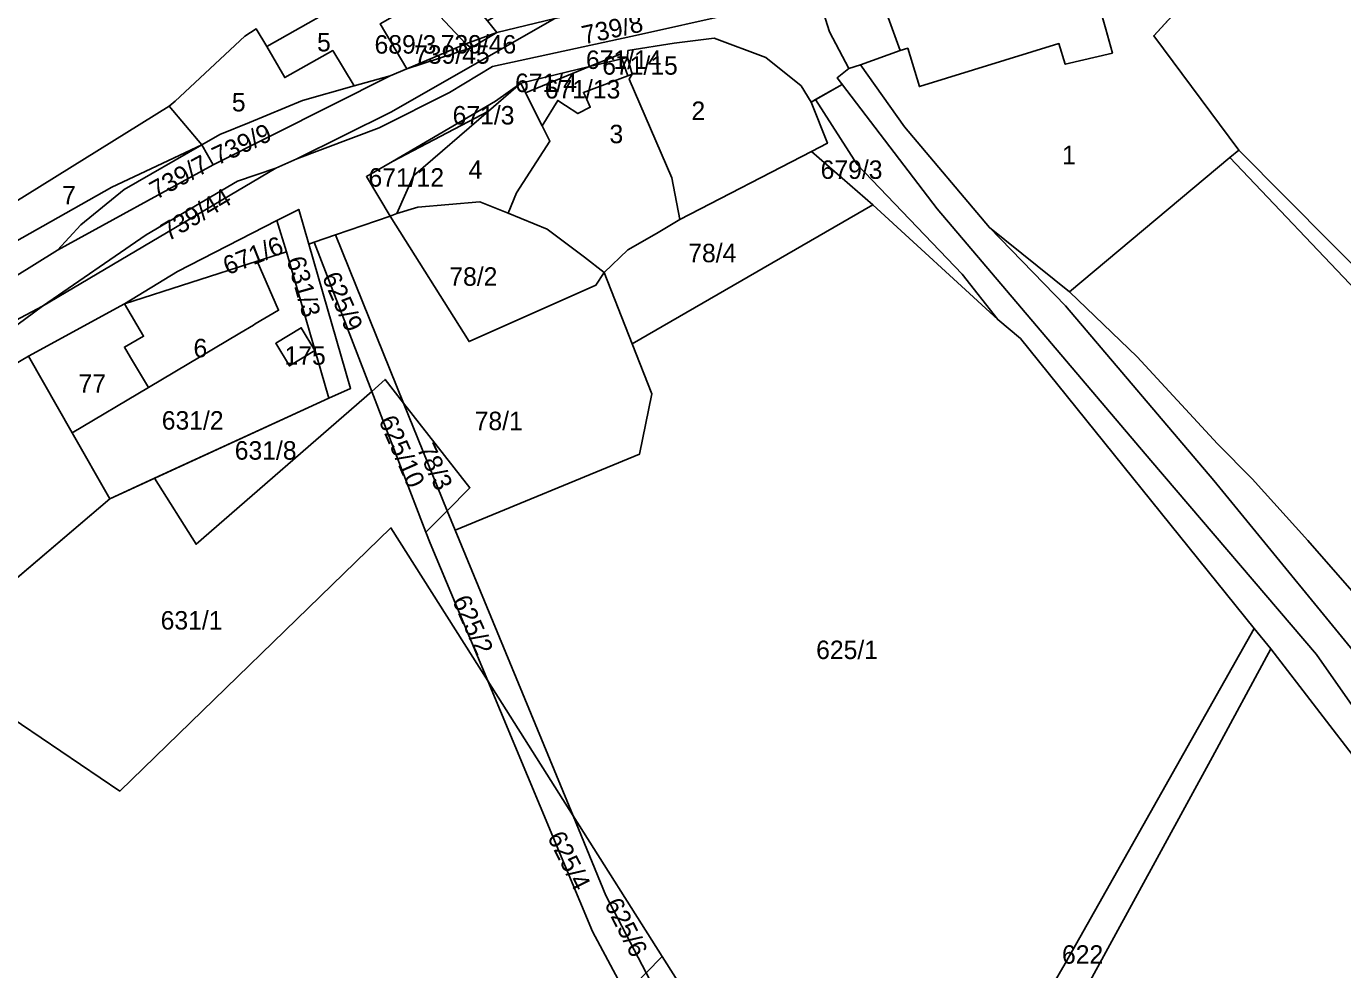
# Model space of a CAD drawing. Extents: x -629983 to -626385, y -1072828 to -1067897.
# Drawn here: x -627150.4 to -626936.7, y -1070299.1 to -1070145.8 of the extents above; entities that cross this region are included whole.
import ezdxf

# ---------------------------------------------------------------- set-up
doc = ezdxf.new("R2010")
doc.units = 0
for name, color, linetype in [('Cesty', 7, 'Continuous'), ('Parcela nároku', 7, 'Continuous'), ('Parcelní číslo', 7, 'Continuous'), ('Plocha PÚ', 7, 'Continuous'), ('Vnitřní obvod_šetřený', 7, 'Continuous')]:
    doc.layers.add(name, color=color, linetype=linetype)

msp = doc.modelspace()

# ---------------------------------------------------------------- linework, layer by layer
at = {"layer": 'Cesty'}
msp.add_lwpolyline([(-626828.5, -1070436.77), (-626845.9, -1070410.76), (-626860.5, -1070382.13), (-626889.8, -1070326.73), (-626898.73, -1070308.1), (-626940.88, -1070247.87), (-626967.82, -1070216.35), (-627002.5, -1070175.45), (-627018.74, -1070154.18)], dxfattribs=at)
at = {"layer": 'Parcela nároku'}
for points in [[(-626967.32, -1070147.34), (-626952.24, -1070130.82), (-626954.18, -1070128.3), (-626936.23, -1070115.91), (-626914.61, -1070101.46), (-626893.72, -1070087.44), (-626878.42, -1070105.68), (-626838.37, -1070153.8), (-626843.54, -1070157.06), (-626848.75, -1070159.57), (-626863.88, -1070171.76), (-626872.99, -1070179.12), (-626887.59, -1070189.96), (-626911.42, -1070210.64), (-626920.06, -1070200.25), (-626930.91, -1070188.7), (-626953.54, -1070165.93)], [(-627179.11, -1070102.43), (-627182.79, -1070129.31), (-627188.17, -1070161.97), (-627164.05, -1070181.7), (-627127.23, -1070158.76), (-627126.21, -1070157.99), (-627114.91, -1070147.41), (-627113.07, -1070146.24), (-627111.33, -1070149.11), (-627095.84, -1070140.28), (-627093.44, -1070138.91), (-627090.01, -1070136.88), (-627090.88, -1070135.94), (-627100.27, -1070127.84), (-627102.93, -1070125.54), (-627123.58, -1070112.62), (-627149.23, -1070101.19), (-627173.72, -1070092.7), (-627175.67, -1070092.02), (-627177.28, -1070091.46)], [(-626969.82, -1070116.29), (-626968.13, -1070119.78), (-626980.11, -1070128.81), (-626979.18, -1070131.84), (-626987.84, -1070134.27), (-626996.76, -1070136.77), (-627011.69, -1070140.96), (-627010.48, -1070144.38), (-627008.5, -1070149.71), (-627014.94, -1070152.06), (-627016.87, -1070152.66), (-627019.96, -1070146.7), (-627021.89, -1070140.64), (-627023.3, -1070136.2), (-627015.8, -1070134.43), (-626983.76, -1070126.87), (-626977.72, -1070122.1)], [(-627100.27, -1070127.84), (-627096.2, -1070123.68), (-627088.83, -1070130.5), (-627081.08, -1070138.25), (-627075.54, -1070144.91), (-627074.02, -1070146.81), (-627079.02, -1070148.65), (-627090.01, -1070136.88), (-627090.88, -1070135.94)], [(-627037.79, -1070128.95), (-627023.44, -1070126.11), (-627017.39, -1070132.64), (-627023.83, -1070134.57), (-627052.84, -1070139.54), (-627057.35, -1070140.58), (-627064.59, -1070144.52), (-627074.02, -1070146.81), (-627075.54, -1070144.91), (-627058.79, -1070134.99)], [(-626982.72, -1070148.62), (-626981.69, -1070151.96), (-626974.05, -1070150.14), (-626975.13, -1070146.29), (-626978.67, -1070133.67), (-626954.18, -1070128.3), (-626952.24, -1070130.82), (-626967.32, -1070147.34), (-626953.54, -1070165.93), (-626954.95, -1070167.11), (-626980.99, -1070188.96), (-626994.01, -1070178.49), (-627007.83, -1070162.13), (-627014.94, -1070152.06), (-627008.5, -1070149.71), (-627007.27, -1070149.36), (-627005.37, -1070155.59)], [(-626979.18, -1070131.84), (-626987.84, -1070134.27), (-626996.76, -1070136.77), (-627011.69, -1070140.96), (-627010.48, -1070144.38), (-627008.5, -1070149.71), (-627007.27, -1070149.36), (-627005.37, -1070155.59), (-626982.72, -1070148.62), (-626981.69, -1070151.96), (-626974.05, -1070150.14), (-626975.13, -1070146.29), (-626978.67, -1070133.67)], [(-627064.59, -1070144.52), (-627091.23, -1070159.74), (-627106.48, -1070167.33), (-627093.12, -1070162.31), (-627081.7, -1070156.55), (-627074.7, -1070152.35), (-627051, -1070147.18), (-627021.89, -1070140.64), (-627023.3, -1070136.2), (-627039.61, -1070139.4)], [(-627093.44, -1070138.91), (-627090.01, -1070136.88), (-627079.02, -1070148.65), (-627088.6, -1070152.71), (-627092.94, -1070145.4), (-627090.54, -1070144.04)], [(-627090.54, -1070144.04), (-627093.44, -1070138.91), (-627095.84, -1070140.28), (-627111.33, -1070149.11), (-627108.45, -1070154.14), (-627100.65, -1070149.75), (-627097.19, -1070155.5), (-627091.34, -1070153.87), (-627088.6, -1070152.71), (-627092.94, -1070145.4)], [(-627114.91, -1070147.41), (-627113.07, -1070146.24), (-627111.33, -1070149.11), (-627108.45, -1070154.14), (-627100.65, -1070149.75), (-627097.19, -1070155.5), (-627105.58, -1070157.84), (-627114.15, -1070161.41), (-627118.97, -1070163.38), (-627121.91, -1070165.06), (-627127.23, -1070158.76), (-627126.21, -1070157.99)], [(-627079.02, -1070148.65), (-627074.02, -1070146.81), (-627078.16, -1070149.32)], [(-627052.52, -1070154.39), (-627052.03, -1070153.59), (-627052.78, -1070150.86), (-627052.71, -1070149.76), (-627045.21, -1070148.52), (-627038.73, -1070147.72), (-627030.34, -1070150.88), (-627024.59, -1070155.47), (-627022.98, -1070158.1), (-627020.32, -1070164.81), (-627022.93, -1070166.16), (-627044.26, -1070177.17), (-627045.61, -1070170.42)], [(-627079.02, -1070148.65), (-627088.6, -1070152.71), (-627078.16, -1070149.32)], [(-627058.98, -1070152.35), (-627053.98, -1070150.32), (-627053.72, -1070151.09)], [(-627070.13, -1070155.02), (-627058.98, -1070152.35), (-627069.34, -1070156.6)], [(-627058.98, -1070152.35), (-627053.72, -1070151.09), (-627052.73, -1070153.85), (-627059.94, -1070156.55), (-627059.55, -1070157.3), (-627058.84, -1070158.94), (-627060.83, -1070159.99), (-627062.86, -1070158.66), (-627064.1, -1070157.85), (-627066.63, -1070161.99), (-627069.34, -1070156.6)], [(-627053.72, -1070151.09), (-627052.78, -1070150.86), (-627052.03, -1070153.59), (-627052.73, -1070153.85)], [(-627118.97, -1070163.38), (-627114.15, -1070161.41), (-627105.58, -1070157.84), (-627097.19, -1070155.5), (-627091.34, -1070153.87), (-627120.06, -1070168.31), (-627121.91, -1070165.06)], [(-627066.63, -1070161.99), (-627064.1, -1070157.85), (-627062.86, -1070158.66), (-627060.83, -1070159.99), (-627058.84, -1070158.94), (-627059.55, -1070157.3), (-627059.94, -1070156.55), (-627052.73, -1070153.85), (-627052.03, -1070153.59), (-627052.52, -1070154.39), (-627045.61, -1070170.42), (-627044.26, -1070177.17), (-627048.1, -1070179.44), (-627052.71, -1070182.12), (-627056.56, -1070185.78), (-627059.79, -1070183.32), (-627065.81, -1070178.73), (-627072.18, -1070176.15), (-627070.8, -1070172.88), (-627065.39, -1070164.46)], [(-627090.97, -1070167.75), (-627074.2, -1070157.96), (-627070.13, -1070155.02), (-627075.38, -1070159.57)], [(-627069.34, -1070156.6), (-627066.63, -1070161.99), (-627065.39, -1070164.46), (-627070.8, -1070172.88), (-627072.18, -1070176.15), (-627076.76, -1070174.29), (-627086.85, -1070175.17), (-627090.24, -1070176.23), (-627087.54, -1070170.08), (-627075.38, -1070159.57), (-627070.13, -1070155.02)], [(-627127.23, -1070158.76), (-627121.91, -1070165.06), (-627136.53, -1070171.95), (-627159.85, -1070185.11), (-627164.05, -1070181.7)], [(-627020.32, -1070164.81), (-627022.93, -1070166.16), (-627012.93, -1070174.79), (-626992.65, -1070193.42), (-626998.42, -1070186.08), (-627015.5, -1070168.26), (-627022.27, -1070157.7), (-627022.98, -1070158.1)], [(-627095.19, -1070170.22), (-627090.97, -1070167.75), (-627075.38, -1070159.57), (-627087.54, -1070170.08), (-627090.24, -1070176.23), (-627091.31, -1070176.64)], [(-627136.53, -1070171.95), (-627159.85, -1070185.11), (-627170.4, -1070190.33), (-627174.26, -1070192.24), (-627196.39, -1070199.83), (-627210.27, -1070201.64), (-627222.24, -1070202.87), (-627223.95, -1070202.72), (-627219.25, -1070207.1), (-627189.73, -1070202.17), (-627183.39, -1070200.59), (-627165.66, -1070194.76), (-627145.34, -1070182.16), (-627141.57, -1070178.04), (-627134.51, -1070172.31), (-627121.91, -1070165.06)], [(-627121.91, -1070165.06), (-627120.06, -1070168.31), (-627145.34, -1070182.16), (-627141.57, -1070178.04), (-627134.51, -1070172.31)], [(-627052.71, -1070182.12), (-627056.56, -1070185.78), (-627052.04, -1070197.4), (-627012.93, -1070174.79), (-627022.93, -1070166.16), (-627044.26, -1070177.17), (-627048.1, -1070179.44)], [(-626933.5, -1070189.76), (-626913.47, -1070212.44), (-626899.9, -1070231.25), (-626865.83, -1070280.61), (-626877.27, -1070289.65), (-626889.89, -1070298.56), (-626917.16, -1070260.49), (-626925.75, -1070248.27), (-626942.33, -1070229.35), (-626951.35, -1070219.33), (-626956.97, -1070213.63), (-626970.02, -1070199.48), (-626980.99, -1070188.96), (-626954.95, -1070167.11)], [(-626954.95, -1070167.11), (-626953.54, -1070165.93), (-626930.91, -1070188.7), (-626920.06, -1070200.25), (-626911.42, -1070210.64), (-626863.34, -1070278.62), (-626865.83, -1070280.61), (-626899.9, -1070231.25), (-626913.47, -1070212.44), (-626933.5, -1070189.76)], [(-627116.09, -1070170.94), (-627109.87, -1070168.86), (-627147.78, -1070191.28), (-627130.96, -1070179.7)], [(-627104.54, -1070181.19), (-627097.76, -1070204.63), (-627101.26, -1070206.23), (-627108.17, -1070182.44), (-627109.71, -1070177.37), (-627106.17, -1070175.55)], [(-627065.81, -1070178.73), (-627059.79, -1070183.32), (-627056.56, -1070185.78), (-627057.9, -1070187.85), (-627078.51, -1070197.03), (-627091.31, -1070176.64), (-627090.24, -1070176.23), (-627086.85, -1070175.17), (-627076.76, -1070174.29), (-627072.18, -1070176.15)], [(-627050.81, -1070215.29), (-627048.81, -1070205.49), (-627052.04, -1070197.4), (-627012.93, -1070174.79), (-626992.65, -1070193.42), (-626988.98, -1070196.53), (-626951.03, -1070243.61), (-626981.69, -1070298.04), (-626996.16, -1070322.96), (-627002.91, -1070334.81), (-627013.07, -1070350.93), (-627019.98, -1070339.74), (-627047.18, -1070296.9), (-627061.62, -1070274.07), (-627080.79, -1070227.64)], [(-627125.88, -1070185.66), (-627109.71, -1070177.37), (-627108.17, -1070182.44), (-627112.91, -1070183.97), (-627134.45, -1070190.91)], [(-627048.81, -1070205.49), (-627052.04, -1070197.4), (-627056.56, -1070185.78), (-627057.9, -1070187.85), (-627078.51, -1070197.03), (-627091.31, -1070176.64), (-627100.2, -1070179.7), (-627089.14, -1070207.02), (-627078.37, -1070220.75), (-627082.06, -1070224.5), (-627080.79, -1070227.64), (-627050.81, -1070215.29)], [(-627103.64, -1070180.88), (-627100.2, -1070179.7), (-627089.14, -1070207.02), (-627092.16, -1070203.17), (-627094.31, -1070205.13)], [(-626970.02, -1070199.48), (-626980.99, -1070188.96), (-626994.01, -1070178.49), (-626981.68, -1070191.23), (-626957.56, -1070219.58), (-626930.04, -1070253.26), (-626911.97, -1070280.03), (-626895.22, -1070304.41), (-626870.89, -1070351.83), (-626851.72, -1070389.73), (-626859.45, -1070367.32), (-626874.57, -1070332.6), (-626889.89, -1070298.56), (-626917.16, -1070260.49), (-626925.75, -1070248.27), (-626942.33, -1070229.35), (-626951.35, -1070219.33), (-626956.97, -1070213.63)], [(-627129.58, -1070219.23), (-627101.26, -1070206.23), (-627097.76, -1070204.63), (-627104.54, -1070181.19), (-627103.64, -1070180.88), (-627094.31, -1070205.13), (-627122.85, -1070229.94)], [(-627115.75, -1070195.67), (-627113.52, -1070194.33), (-627113.22, -1070194.15), (-627109.44, -1070191.92), (-627112.91, -1070183.97), (-627108.17, -1070182.44), (-627101.26, -1070206.23), (-627129.58, -1070219.23), (-627136.82, -1070222.55), (-627142.96, -1070211.82), (-627130.55, -1070204.49)], [(-627109.44, -1070191.92), (-627112.91, -1070183.97), (-627134.45, -1070190.91), (-627131.36, -1070196.16), (-627134.47, -1070197.91), (-627133.47, -1070199.59), (-627130.55, -1070204.49), (-627115.75, -1070195.67), (-627113.52, -1070194.33), (-627113.22, -1070194.15)], [(-627131.36, -1070196.16), (-627134.45, -1070190.91), (-627150.06, -1070199.41), (-627142.96, -1070211.82), (-627130.55, -1070204.49), (-627133.47, -1070199.59), (-627134.47, -1070197.91)], [(-627179.8, -1070206.02), (-627168.73, -1070201.81), (-627160.19, -1070197.81), (-627147.78, -1070191.28), (-627155.94, -1070197.27), (-627159.18, -1070199.17), (-627167.6, -1070202.27)], [(-627109.89, -1070197.28), (-627107.68, -1070200.96), (-627103.56, -1070198.46), (-627105.75, -1070194.77)], [(-627103.56, -1070198.46), (-627105.75, -1070194.77), (-627109.89, -1070197.28), (-627107.68, -1070200.96)], [(-627142.96, -1070211.82), (-627150.06, -1070199.41), (-627169.23, -1070210.68), (-627177.05, -1070215.28), (-627174.92, -1070218.64), (-627172.45, -1070222.54), (-627179.99, -1070226.51), (-627181.9, -1070223.57), (-627182.47, -1070223.92), (-627184.95, -1070219.92), (-627189.44, -1070222.56), (-627167.2, -1070248.39), (-627136.82, -1070222.55)], [(-627092.16, -1070203.17), (-627089.14, -1070207.02), (-627082.06, -1070224.5), (-627085.51, -1070227.99), (-627094.31, -1070205.13)], [(-627094.31, -1070205.13), (-627085.51, -1070227.99), (-627084.83, -1070229.76), (-627075.48, -1070252.15), (-627091.2, -1070227.3), (-627135.2, -1070270.05), (-627167.2, -1070248.39), (-627136.82, -1070222.55), (-627129.58, -1070219.23), (-627122.85, -1070229.94)], [(-627089.14, -1070207.02), (-627078.37, -1070220.75), (-627082.06, -1070224.5)], [(-627082.06, -1070224.5), (-627085.51, -1070227.99), (-627084.83, -1070229.76), (-627075.48, -1070252.15), (-627061.62, -1070274.07), (-627080.79, -1070227.64)], [(-626951.03, -1070243.61), (-626948.34, -1070246.95), (-626957.81, -1070264.45), (-626978.64, -1070302.67), (-626999.11, -1070339.24), (-627007.09, -1070354.1), (-627011.37, -1070355.84), (-627013.07, -1070350.93), (-627002.91, -1070334.81), (-626996.16, -1070322.96), (-626981.69, -1070298.04)], [(-627075.48, -1070252.15), (-627061.62, -1070274.07), (-627056.32, -1070287), (-627049.73, -1070299.54), (-627053.04, -1070302.96), (-627058.48, -1070292.86)], [(-627061.62, -1070274.07), (-627047.18, -1070296.9), (-627049.73, -1070299.54), (-627056.32, -1070287)], [(-627047.18, -1070296.9), (-627049.73, -1070299.54), (-627029.32, -1070338.39), (-627020.26, -1070353.28), (-627009.85, -1070374.79), (-626988.77, -1070416.53), (-626959.42, -1070473.41), (-626956.06, -1070461.5), (-626987.37, -1070402.95), (-627011.37, -1070355.84), (-627013.07, -1070350.93), (-627019.98, -1070339.74)]]:
    msp.add_lwpolyline(points, close=True, dxfattribs=at)
for points in [[(-627155.94, -1070197.27), (-627147.78, -1070191.28), (-627109.87, -1070168.86), (-627106.48, -1070167.33), (-627093.12, -1070162.31), (-627081.7, -1070156.55), (-627074.7, -1070152.35), (-627051, -1070147.18), (-627021.89, -1070140.64), (-627019.96, -1070146.7), (-627016.87, -1070152.66), (-627018.74, -1070154.18), (-627017.93, -1070155.27), (-627022.27, -1070157.7), (-627022.98, -1070158.1), (-627024.59, -1070155.47), (-627030.34, -1070150.88), (-627038.73, -1070147.72), (-627045.21, -1070148.52), (-627052.71, -1070149.76), (-627052.78, -1070150.86), (-627053.72, -1070151.09), (-627053.98, -1070150.32), (-627058.98, -1070152.35), (-627070.13, -1070155.02), (-627074.2, -1070157.96), (-627090.97, -1070167.75), (-627095.19, -1070170.22), (-627091.31, -1070176.64), (-627100.2, -1070179.7), (-627103.64, -1070180.88), (-627104.54, -1070181.19), (-627106.17, -1070175.55), (-627109.71, -1070177.37), (-627125.88, -1070185.66), (-627134.45, -1070190.91), (-627150.06, -1070199.41), (-627169.23, -1070210.68)], [(-627165.66, -1070194.76), (-627145.34, -1070182.16), (-627120.06, -1070168.31), (-627091.34, -1070153.87), (-627088.6, -1070152.71), (-627078.16, -1070149.32), (-627074.02, -1070146.81), (-627064.59, -1070144.52), (-627091.23, -1070159.74), (-627106.48, -1070167.33), (-627109.87, -1070168.86), (-627116.09, -1070170.94), (-627130.96, -1070179.7), (-627147.78, -1070191.28), (-627160.19, -1070197.81)], [(-626930.04, -1070253.26), (-626957.56, -1070219.58), (-626981.68, -1070191.23), (-626994.01, -1070178.49), (-627007.83, -1070162.13), (-627014.94, -1070152.06), (-627016.87, -1070152.66), (-627018.74, -1070154.18), (-627017.93, -1070155.27), (-627022.27, -1070157.7), (-627015.5, -1070168.26), (-626998.42, -1070186.08), (-626992.65, -1070193.42), (-626988.98, -1070196.53), (-626951.03, -1070243.61), (-626948.34, -1070246.95), (-626933.51, -1070266.22)], [(-627272.9, -1070414.5), (-627263.63, -1070404.64), (-627253.21, -1070383.58), (-627237.32, -1070342.02), (-627236.14, -1070341.15), (-627204.91, -1070305.64), (-627187.83, -1070282.28), (-627184.44, -1070277.62), (-627184.08, -1070275.66), (-627182.9, -1070269.22), (-627183.96, -1070265.49), (-627167.2, -1070248.39), (-627135.2, -1070270.05), (-627091.2, -1070227.3), (-627075.48, -1070252.15), (-627058.48, -1070292.86), (-627053.04, -1070302.96), (-627152.6, -1070406.05), (-627254.93, -1070512.01), (-627269.4, -1070505.83), (-627296.3, -1070493.2)], [(-626911.31, -1070492.3), (-626939.59, -1070512.67), (-626959.42, -1070473.41), (-626956.06, -1070461.5), (-626987.37, -1070402.95), (-627011.37, -1070355.84), (-627007.09, -1070354.1), (-626999.11, -1070339.24), (-626978.64, -1070302.67), (-626957.81, -1070264.45), (-626948.34, -1070246.95), (-626933.51, -1070266.22)]]:
    msp.add_lwpolyline(points, dxfattribs=at)
at = {"layer": 'Plocha PÚ'}
msp.add_lwpolyline([(-626952.24, -1070130.82), (-626967.32, -1070147.34), (-626953.54, -1070165.93), (-626954.95, -1070167.11), (-626980.99, -1070188.96), (-626994.01, -1070178.49), (-627007.83, -1070162.13), (-627014.94, -1070152.06), (-627016.87, -1070152.66), (-627018.74, -1070154.18), (-627017.93, -1070155.27), (-627022.27, -1070157.7), (-627022.98, -1070158.1), (-627020.32, -1070164.81), (-627022.93, -1070166.16), (-627044.26, -1070177.17), (-627048.1, -1070179.44), (-627052.71, -1070182.12), (-627056.56, -1070185.78), (-627057.9, -1070187.85), (-627078.51, -1070197.03), (-627091.31, -1070176.64), (-627100.2, -1070179.7), (-627103.64, -1070180.88), (-627104.54, -1070181.19), (-627097.76, -1070204.63), (-627101.26, -1070206.23), (-627129.58, -1070219.23), (-627136.82, -1070222.55), (-627167.2, -1070248.39)], dxfattribs=at)
at = {"layer": 'Vnitřní obvod_šetřený'}
for p, q in [((-626952.24, -1070130.82), (-626967.32, -1070147.34)), ((-626967.32, -1070147.34), (-626953.54, -1070165.93)), ((-627014.94, -1070152.06), (-627016.87, -1070152.66)), ((-627007.83, -1070162.13), (-627014.94, -1070152.06)), ((-627016.87, -1070152.66), (-627018.74, -1070154.18)), ((-627018.74, -1070154.18), (-627017.93, -1070155.27)), ((-627017.93, -1070155.27), (-627022.98, -1070158.1)), ((-627022.98, -1070158.1), (-627020.32, -1070164.81)), ((-626994.01, -1070178.49), (-627007.83, -1070162.13)), ((-627020.32, -1070164.81), (-627022.93, -1070166.16)), ((-627022.93, -1070166.16), (-627044.26, -1070177.17)), ((-626954.95, -1070167.11), (-626980.99, -1070188.96)), ((-626953.54, -1070165.93), (-626954.95, -1070167.11)), ((-627091.31, -1070176.64), (-627100.2, -1070179.7)), ((-627078.51, -1070197.03), (-627091.31, -1070176.64)), ((-627044.26, -1070177.17), (-627048.1, -1070179.44)), ((-627100.2, -1070179.7), (-627103.64, -1070180.88)), ((-627048.1, -1070179.44), (-627052.71, -1070182.12)), ((-626980.99, -1070188.96), (-626994.01, -1070178.49)), ((-627103.64, -1070180.88), (-627104.54, -1070181.19)), ((-627104.54, -1070181.19), (-627097.76, -1070204.63)), ((-627052.71, -1070182.12), (-627056.56, -1070185.78)), ((-627056.56, -1070185.78), (-627057.9, -1070187.85)), ((-627057.9, -1070187.85), (-627078.51, -1070197.03)), ((-627097.76, -1070204.63), (-627101.26, -1070206.23)), ((-627101.26, -1070206.23), (-627136.82, -1070222.55)), ((-627136.82, -1070222.55), (-627167.2, -1070248.39))]:
    msp.add_line(p, q, dxfattribs=at)

# ---------------------------------------------------------------- texts
at = {"layer": 'Parcelní číslo'}
for s, rotation, p in [('739/8', 12.4881, (-627059.84, -1070148.76)), ('739/9', 25.0045, (-627119.35, -1070168.43)), ('739/7', 28.7797, (-627129.32, -1070174.01)), ('739/44', 30.7444, (-627127.37, -1070180.79)), ('671/6', 21.5226, (-627117.72, -1070186.26)), ('631/3', 285.744, (-627108.16, -1070183.65)), ('625/9', 293.9452, (-627102.45, -1070186.52)), ('625/10', 293.6693, (-627093.25, -1070209.82)), ('78/3', 294.6721, (-627087.05, -1070214.39)), ('625/2', 294.0687, (-627081.3, -1070239.04)), ('625/4', 296.9171, (-627065.87, -1070277.52)), ('625/6', 297.0929, (-627056.62, -1070288.36))]:
    msp.add_text(s, height=3, rotation=rotation, dxfattribs=at).set_placement(p)
for s, p in [('5', (-627103.2, -1070149.88)), ('689/3', (-627093.86, -1070150.24)), ('739/46', (-627083.12, -1070150.23)), ('739/45', (-627087.43, -1070151.88)), ('671/14', (-627059.53, -1070152.73)), ('671/15', (-627056.89, -1070153.66)), ('671/4', (-627071.03, -1070156.48)), ('671/13', (-627066.22, -1070157.53)), ('5', (-627117.03, -1070159.63)), ('671/3', (-627081.18, -1070161.75)), ('2', (-627042.4, -1070161.02)), ('3', (-627055.71, -1070164.8)), ('1', (-626982.23, -1070168.2)), ('679/3', (-627021.42, -1070170.59)), ('671/12', (-627094.84, -1070171.85)), ('4', (-627078.59, -1070170.58)), ('7', (-627144.58, -1070174.72)), ('78/4', (-627042.92, -1070184.13)), ('78/2', (-627081.72, -1070187.95)), ('6', (-627123.26, -1070199.57)), ('175', (-627108.48, -1070200.79)), ('77', (-627141.93, -1070205.34)), ('631/2', (-627128.41, -1070211.32)), ('78/1', (-627077.6, -1070211.41)), ('631/8', (-627116.56, -1070216.2)), ('631/1', (-627128.59, -1070243.8)), ('625/1', (-627022.15, -1070248.59)), ('622', (-626982.23, -1070298.08))]:
    msp.add_text(s, height=3, dxfattribs=at).set_placement(p)

doc.saveas('drawing.dxf')
